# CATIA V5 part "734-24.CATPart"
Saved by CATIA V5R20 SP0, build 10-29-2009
Part number: 734-24
Bounding box of the stored display mesh (mm): x -24 to 24, y -23.94 to 23.94, z -30 to 50
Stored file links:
  C:\Users\Utente\Desktop\IO LAVORO\3D X SITO CF\X SITO\734\734-24.CATPart
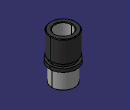
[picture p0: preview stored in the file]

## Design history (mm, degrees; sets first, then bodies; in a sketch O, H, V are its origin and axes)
Set1
  DatumSurface1 to DatumSurface25 "734-24"
Body1 (main body)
